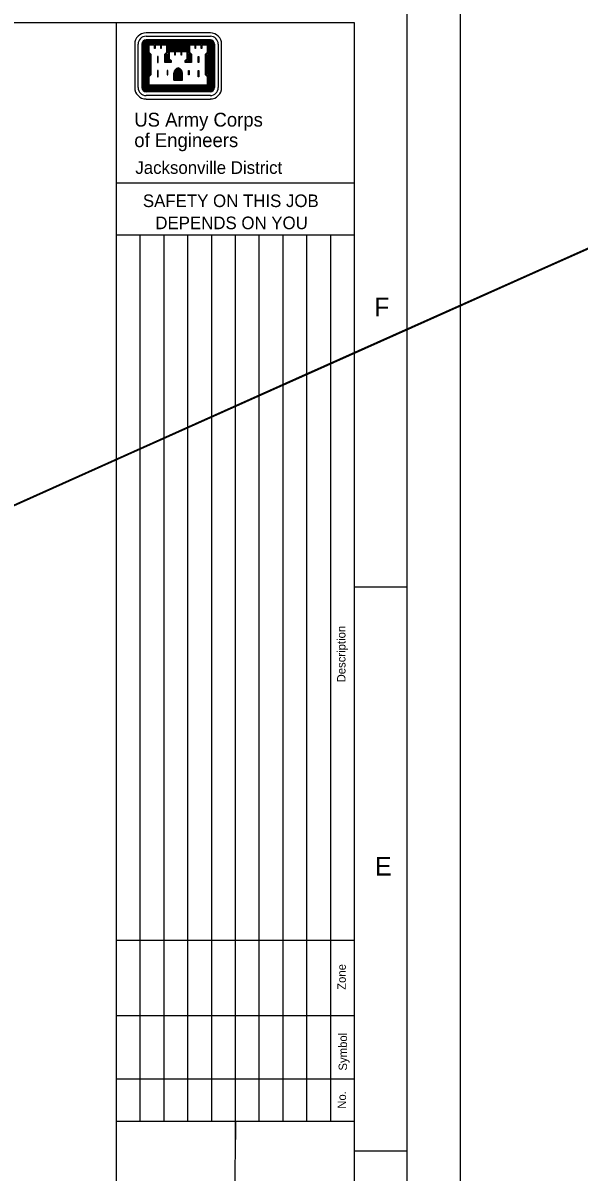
# Model space of a CAD drawing. Extents: x -295500 to 4194304, y 88492 to 2097152.
# Drawn here: x 1114915 to 1141196, y 687787 to 742112 of the extents above; entities that cross this region are included whole.
import ezdxf

# ---------------------------------------------------------------- set-up
doc = ezdxf.new("R2010")
doc.units = 0
for name, color, linetype in [('G-ANNO-NPLT', 7, 'Continuous'), ('G-ANNO-TEXT-LOGO', 7, 'Continuous'), ('G-ANNO-TEXT-TTLB', 7, 'Continuous'), ('G-ANNO-TTLB', 7, 'Continuous'), ('V-ANNO-SYMB', 7, 'Continuous')]:
    doc.layers.add(name, color=color, linetype=linetype)

msp = doc.modelspace()

# ---------------------------------------------------------------- linework, layer by layer
at = {"layer": 'G-ANNO-NPLT'}
msp.add_lwpolyline([(915578.8187059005, 747112.0946896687), (1135577.4987076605, 747112.0946896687), (1135577.4987076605, 577113.1146883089), (915578.8187059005, 577113.1146883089)], close=True, dxfattribs=at)
at = {"layer": 'G-ANNO-TEXT-LOGO'}
for p, q in [((1123770.5162011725, 741642.7534749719), (1120730.534441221, 741642.7534749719)), ((1120195.5376511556, 741107.7566849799), (1120195.5376511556, 739057.7689849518)), ((1120355.53669113, 739057.7689849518), (1120355.53669113, 741107.7566849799)), ((1120530.5356411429, 741107.7566849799), (1120530.5356411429, 739057.7689849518)), ((1120575.5353712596, 741107.7566849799), (1120575.5353712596, 739057.7689849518)), ((1120615.5351312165, 741107.7566849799), (1120615.5351312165, 739057.7689849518)), ((1120660.5348611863, 741107.7566849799), (1120660.5348611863, 739057.7689849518)), ((1120705.534591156, 741107.7566849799), (1120705.534591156, 739057.7689849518)), ((1120730.534441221, 741482.7544349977), (1123770.5162011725, 741482.7544349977)), ((1123770.5162011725, 741312.7554549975), (1120730.534441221, 741312.7554549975)), ((1123770.5162011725, 741267.7557250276), (1120730.534441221, 741267.7557250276)), ((1123770.5162011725, 741222.7559949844), (1120730.534441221, 741222.7559949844)), ((1123770.5162011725, 741182.7562350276), (1120730.534441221, 741182.7562350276)), ((1123770.5162011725, 741137.7565049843), (1120730.534441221, 741137.7565049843)), ((1120750.534321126, 741107.7566849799), (1120750.534321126, 739072.7688949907)), ((1120790.5340812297, 741107.7566849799), (1120790.5340812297, 739117.7686249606)), ((1121785.5281111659, 741097.7567450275), (1122715.5225312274, 741097.7567450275)), ((1121785.5281111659, 741052.7570149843), (1122715.5225312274, 741052.7570149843)), ((1121785.5281111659, 741012.7572550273), (1122715.5225312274, 741012.7572550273)), ((1123710.5165611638, 741107.7566849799), (1123710.5165611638, 739117.7686249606)), ((1123750.5163212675, 741107.7566849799), (1123750.5163212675, 739072.7688949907)), ((1123795.5160512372, 741107.7566849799), (1123795.5160512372, 739057.7689849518)), ((1123840.515781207, 741107.7566849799), (1123840.515781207, 739057.7689849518)), ((1123880.515541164, 741107.7566849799), (1123880.515541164, 739057.7689849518)), ((1123925.5152712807, 741107.7566849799), (1123925.5152712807, 739057.7689849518)), ((1123970.5150012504, 741107.7566849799), (1123970.5150012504, 739057.7689849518)), ((1124140.5139812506, 741107.7566849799), (1124140.5139812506, 739057.7689849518)), ((1124305.5129912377, 739057.7689849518), (1124305.5129912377, 741107.7566849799)), ((1120825.5338711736, 740672.7592950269), (1120825.5338711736, 739622.7655950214)), ((1120870.5336011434, 740627.7595649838), (1120870.5336011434, 739672.7652950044)), ((1121785.5281111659, 740967.7575249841), (1122715.5225312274, 740967.7575249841)), ((1121785.5281111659, 740922.7577950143), (1122715.5225312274, 740922.7577950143)), ((1121785.5281111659, 740882.758034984), (1122715.5225312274, 740882.758034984)), ((1121785.5281111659, 740837.7583050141), (1122715.5225312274, 740837.7583050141)), ((1123630.51704125, 740627.7595649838), (1123630.51704125, 739672.7652950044)), ((1123675.51677122, 740667.7593250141), (1123675.51677122, 739627.7655649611)), ((1122050.5265212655, 739412.7668549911), (1122050.5265212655, 739747.7648449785)), ((1122050.5265212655, 739412.7668549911), (1122450.5241212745, 739412.7668549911)), ((1122090.5262812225, 739412.7668549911), (1122090.5262812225, 739747.7648449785)), ((1122135.5260111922, 739412.7668549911), (1122135.5260111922, 739747.7648449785)), ((1122180.525741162, 739412.7668549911), (1122180.525741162, 739747.7648449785)), ((1122220.5255012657, 739412.7668549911), (1122220.5255012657, 739747.7648449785)), ((1122280.5251411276, 739412.7668549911), (1122280.5251411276, 739747.7648449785)), ((1122320.5249012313, 739412.7668549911), (1122320.5249012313, 739747.7648449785)), ((1122365.524631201, 739412.7668549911), (1122365.524631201, 739747.7648449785)), ((1122410.524361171, 739412.7668549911), (1122410.524361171, 739747.7648449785)), ((1122450.5241212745, 739412.7668549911), (1122450.5241212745, 739747.7648449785)), ((1123770.5162011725, 739027.7691650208), (1120730.534441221, 739027.7691650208)), ((1123770.5162011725, 738987.7694049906), (1120730.534441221, 738987.7694049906)), ((1123770.5162011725, 738942.7696750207), (1120730.534441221, 738942.7696750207)), ((1123770.5162011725, 738897.7699449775), (1120730.534441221, 738897.7699449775)), ((1123770.5162011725, 738857.7701850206), (1120730.534441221, 738857.7701850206)), ((1123750.5163212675, 739072.7688949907), (1120750.534321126, 739072.7688949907)), ((1123710.5165611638, 739117.7686249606), (1120790.5340812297, 739117.7686249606)), ((1123770.5162011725, 738682.7712350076), (1120730.534441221, 738682.7712350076)), ((1120730.534441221, 738517.7722249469), (1123770.5162011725, 738517.7722249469))]:
    msp.add_line(p, q, dxfattribs=at)
for points in [[(1120825.5338711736, 741107.7566849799), (1120825.5338711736, 740712.7590549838), (1120910.533361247, 740627.7595649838), (1120910.533361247, 739672.7652950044), (1120825.5338711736, 739582.7658349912), (1120825.5338711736, 739147.7684449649), (1123675.51677122, 739147.7684449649), (1123675.51677122, 739582.7658349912), (1123585.5173112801, 739672.7652950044), (1123585.5173112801, 740627.7595649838), (1123675.51677122, 740712.7590549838), (1123675.51677122, 741107.7566849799), (1123300.5190212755, 741107.7566849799), (1123010.5207612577, 741107.7566849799), (1122740.5223811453, 741107.7566849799), (1122740.5223811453, 740712.7590549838), (1122835.5218112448, 740627.7595649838), (1122835.5218112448, 740277.7616650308), (1122625.523071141, 740277.7616650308), (1122625.523071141, 740312.7614549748), (1122715.5225312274, 740402.7609149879), (1122715.5225312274, 740792.758574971), (1122340.5247811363, 740792.758574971), (1122050.5265212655, 740792.758574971), (1121785.5281111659, 740792.758574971), (1121785.5281111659, 740402.7609149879), (1121875.5275712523, 740312.7614549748), (1121875.5275712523, 740277.7616650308), (1121665.5288311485, 740277.7616650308), (1121665.5288311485, 740627.7595649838), (1121755.528291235, 740712.7590549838), (1121755.528291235, 741107.7566849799), (1121380.5305411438, 741107.7566849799), (1121090.5322811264, 741107.7566849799), (1120825.5338711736, 741107.7566849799)], [(1120865.5336311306, 741062.7569550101), (1120865.5336311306, 740732.7589350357), (1120955.5330912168, 740642.7594750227), (1120955.5330912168, 739652.7654150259), (1120865.5336311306, 739562.7659550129), (1120865.5336311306, 739192.768175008), (1123635.517011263, 739192.768175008), (1123635.517011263, 739562.7659550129), (1123540.5175811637, 739652.7654150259), (1123540.5175811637, 740642.7594750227), (1123635.517011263, 740732.7589350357), (1123635.517011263, 741062.7569550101), (1123365.5186311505, 741062.7569550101), (1123365.5186311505, 740907.7578849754), (1123340.5187812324, 740907.7578849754), (1123340.5187812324, 741062.7569550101), (1123075.5203712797, 741062.7569550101), (1123075.5203712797, 740907.7578849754), (1123055.5204912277, 740907.7578849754), (1123055.5204912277, 741062.7569550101), (1122785.522111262, 741062.7569550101), (1122785.522111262, 740732.7589350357), (1122875.5215712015, 740642.7594750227), (1122875.5215712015, 740237.7619050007), (1122585.523311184, 740237.7619050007), (1122585.523311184, 740332.7613350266), (1122675.5227712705, 740422.7607949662), (1122675.5227712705, 740752.7588150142), (1122405.524391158, 740752.7588150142), (1122405.524391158, 740597.7597449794), (1122385.5245112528, 740597.7597449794), (1122385.5245112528, 740752.7588150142), (1122115.5261311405, 740752.7588150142), (1122115.5261311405, 740597.7597449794), (1122090.5262812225, 740597.7597449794), (1122090.5262812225, 740752.7588150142), (1121825.5278712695, 740752.7588150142), (1121825.5278712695, 740422.7607949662), (1121915.5273312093, 740332.7613350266), (1121915.5273312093, 740237.7619050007), (1121625.5290711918, 740237.7619050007), (1121625.5290711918, 740642.7594750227), (1121715.5285311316, 740732.7589350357), (1121715.5285311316, 741062.7569550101), (1121450.5301211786, 741062.7569550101), (1121450.5301211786, 740907.7578849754), (1121425.5302712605, 740907.7578849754), (1121425.5302712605, 741062.7569550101), (1121155.531891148, 741062.7569550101), (1121155.531891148, 740907.7578849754), (1121135.532011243, 740907.7578849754), (1121135.532011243, 741062.7569550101), (1120865.5336311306, 741062.7569550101)], [(1121275.5311711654, 740527.7601650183), (1121275.5311711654, 740237.7619050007), (1121305.530991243, 740237.7619050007), (1121305.530991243, 740527.7601650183), (1121275.5311711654, 740527.7601650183)], [(1121735.5284111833, 740632.7595349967), (1121710.528561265, 740607.7596850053), (1121710.528561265, 740322.7613950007), (1121805.5279912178, 740322.7613950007), (1121740.528381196, 740387.7610050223), (1121740.528381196, 740637.7595050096)], [(1122765.5222312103, 740632.7595349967), (1122790.5220812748, 740607.7596850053), (1122790.5220812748, 740322.7613950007), (1122700.5226211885, 740322.7613950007), (1122760.5222611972, 740387.7610050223), (1122760.5222611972, 740637.7595050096)], [(1123220.519501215, 740527.7601650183), (1123220.519501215, 740237.7619050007), (1123195.5196511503, 740237.7619050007), (1123195.5196511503, 740527.7601650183), (1123220.519501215, 740527.7601650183)], [(1121275.5311711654, 739862.7641549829), (1121275.5311711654, 739567.7659250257), (1121305.530991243, 739567.7659250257), (1121305.530991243, 739862.7641549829), (1121275.5311711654, 739862.7641549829)], [(1121735.5284111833, 739862.7641549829), (1121735.5284111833, 739657.7653849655), (1121760.528261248, 739657.7653849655), (1121760.528261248, 739862.7641549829), (1121735.5284111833, 739862.7641549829)], [(1122765.5222312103, 739862.7641549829), (1122765.5222312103, 739657.7653849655), (1122740.5223811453, 739657.7653849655), (1122740.5223811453, 739862.7641549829), (1122765.5222312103, 739862.7641549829)], [(1123220.519501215, 739862.7641549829), (1123220.519501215, 739567.7659250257), (1123195.5196511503, 739567.7659250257), (1123195.5196511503, 739862.7641549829), (1123220.519501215, 739862.7641549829)]]:
    msp.add_lwpolyline(points, dxfattribs=at)
for centre, major_axis, ratio, start_param, end_param in [((1120731.8048306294, 741108.6151385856), (535.6894959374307, 0), 0.99963998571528, 1.5707800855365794, 3.141576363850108), ((1123767.3785251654, 741108.5674731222), (535.6894959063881, 0), 0.9996399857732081, 6.283169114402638, 7.853965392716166), ((1120731.8048306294, 741108.6151385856), (374.4914271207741, 0), 0.9996399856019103, 1.5707800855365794, 3.141576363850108), ((1120731.8048306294, 741108.6151385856), (200.8836685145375, 0), 0.9996399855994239, 1.5707800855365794, 3.141576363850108), ((1120731.8048306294, 741108.6151385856), (157.4827590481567, 0), 0.9996399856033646, 1.5707800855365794, 3.141576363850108), ((1120731.8048306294, 741108.6151385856), (114.08194856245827, 0), 0.9996399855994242, 1.5707800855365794, 3.141576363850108), ((1120731.8048306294, 741108.6151385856), (70.68113475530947, 0), 0.9996399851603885, 1.5707800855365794, 3.141576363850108), ((1120731.8048306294, 741108.6151385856), (27.280320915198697, 0), 0.9996399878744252, 1.5707800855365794, 3.141576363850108), ((1123767.3785251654, 741108.5674731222), (27.280320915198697, 0), 0.9996399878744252, 6.283169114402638, 7.853965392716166), ((1123767.3785251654, 741108.5674731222), (70.68113466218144, 0), 0.999639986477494, 6.283169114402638, 7.853965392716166), ((1123767.3785251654, 741108.5674731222), (114.08194846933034, 0), 0.9996399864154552, 6.283169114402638, 7.853965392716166), ((1123767.3785251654, 741108.5674731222), (157.48275895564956, 0), 0.9996399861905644, 6.283169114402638, 7.853965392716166), ((1123767.3785251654, 741108.5674731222), (200.88366842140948, 0), 0.9996399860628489, 6.283169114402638, 7.853965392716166), ((1123767.3785251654, 741108.5674731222), (374.49142660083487, 0), 0.9996399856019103, 6.283169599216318, 7.853965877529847), ((1122324.3599183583, 739725.4688298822), (-277.6705194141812, 3.4004831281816e-14), 0.9996399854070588, 4.9858321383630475, 6.214359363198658), ((1122324.3599183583, 739725.4688298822), (-234.2697347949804, 2.8689768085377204e-14), 0.9996399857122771, 4.947465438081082, 6.214359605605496), ((1122174.779969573, 739725.4711786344), (234.2697368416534, 0), 0.9996399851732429, 0.06879472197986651, 1.335688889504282), ((1122174.779969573, 739725.4711786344), (277.6705215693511, 0), 0.9996399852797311, 0.06879467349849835, 1.298419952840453), ((1122324.3599183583, 739725.4688298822), (-190.86890076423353, 2.337469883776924e-14), 0.9996399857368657, 4.947465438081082, 6.214359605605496), ((1122324.3599183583, 739725.4688298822), (-147.4681138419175, 1.8059635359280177e-14), 0.9996399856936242, 4.9474653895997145, 6.21435955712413), ((1122174.779969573, 739725.4711786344), (104.0672750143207, 0), 0.9996399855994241, 0.06879443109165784, 1.3356885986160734), ((1122174.779969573, 739725.4711786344), (147.46811562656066, 0), 0.9996399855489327, 0.068794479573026, 1.3356886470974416), ((1122174.779969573, 739725.4711786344), (190.86890273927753, 0), 0.9996399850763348, 0.06879481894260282, 1.3356889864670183), ((1122324.3599183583, 739725.4688298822), (-104.06727339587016, 1.274456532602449e-14), 0.9996399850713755, 4.947464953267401, 6.2143591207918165), ((1120731.772574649, 739055.879026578), (-535.6894941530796, 6.560304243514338e-14), 0.999639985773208, 6.283170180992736, 7.853966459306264), ((1120731.772574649, 739055.879026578), (-374.49142660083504, 4.586197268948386e-14), 0.9996399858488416, 6.283169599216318, 7.853965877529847), ((1120731.772574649, 739055.879026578), (-200.88366785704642, 2.4601154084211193e-14), 0.9996399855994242, 6.2831701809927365, 7.853966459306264), ((1120731.772574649, 739055.879026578), (-157.48275853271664, 1.9286075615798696e-14), 0.9996399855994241, 6.2831701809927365, 7.853966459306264), ((1120731.772574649, 739055.879026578), (-114.08194809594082, 1.3971009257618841e-14), 0.9996399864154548, 6.2831701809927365, 7.853966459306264), ((1120731.772574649, 739055.879026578), (-70.68113443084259, 8.655942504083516e-15), 0.9996399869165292, 6.2831701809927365, 7.853966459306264), ((1120731.772574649, 739055.879026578), (-27.280320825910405, 3.3408757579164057e-15), 0.999639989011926, 6.2831701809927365, 7.853966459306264), ((1123767.346269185, 739055.8313609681), (535.6894952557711, 0), 0.9996399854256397, 4.71237332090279, 6.283169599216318), ((1123767.346269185, 739055.8313609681), (-374.49142589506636, 4.5861972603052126e-14), 0.9996399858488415, 1.570781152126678, 3.1415774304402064), ((1123767.346269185, 739055.8313609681), (200.88366823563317, 0), 0.9996399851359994, 4.71237332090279, 6.283169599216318), ((1123767.346269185, 739055.8313609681), (157.4827588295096, 0), 0.999639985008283, 4.71237332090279, 6.283169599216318), ((1123767.346269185, 739055.8313609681), (114.08194840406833, 0), 0.9996399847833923, 4.71237332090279, 6.283169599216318), ((1123767.346269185, 739055.8313609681), (70.68113465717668, 0), 0.9996399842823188, 4.71237332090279, 6.283169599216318), ((1123767.346269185, 739055.8313609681), (27.280320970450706, 0), 0.9996399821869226, 4.71237332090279, 6.283169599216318)]:
    msp.add_ellipse(centre, major_axis=major_axis, ratio=ratio, start_param=start_param, end_param=end_param, dxfattribs=at)
at = {"layer": 'G-ANNO-TTLB'}
for p, q in [((1119326.1851971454, 742112.1246896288), (1119326.1851971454, 582113.0846883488)), ((1119327.5962075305, 734550.5892127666), (1130577.5287076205, 734550.5892127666)), ((1119296.8200647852, 732094.4645139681), (1130546.7525648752, 732094.4645139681)), ((1120443.0284441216, 732094.4645139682), (1120443.0284441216, 690198.7862496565)), ((1121568.0239441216, 732094.4645139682), (1121568.0239441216, 690198.7862496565)), ((1122693.0194441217, 732094.4645139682), (1122693.0194441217, 690198.7862496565)), ((1123818.0149441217, 732094.4645139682), (1123818.0149441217, 690198.7862496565)), ((1124943.0104441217, 732094.4645139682), (1124943.0104441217, 690198.7862496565)), ((1126068.0059441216, 732094.4645139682), (1126068.0059441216, 690198.7862496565)), ((1127193.0014441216, 732094.4645139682), (1127193.0014441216, 690198.7862496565)), ((1128317.9969441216, 732094.4645139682), (1128317.9969441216, 690198.7862496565)), ((1129442.9924441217, 732094.4645139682), (1129442.9924441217, 690198.7862496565)), ((1133077.5137076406, 715437.0655515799), (1130577.5287076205, 715437.0655515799)), ((1119327.5962075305, 698750.2562425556), (1130577.5287076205, 698750.2562425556)), ((1119327.5962075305, 695191.5190431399), (1130577.5287076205, 695191.5190431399)), ((1119327.5962075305, 692191.5370430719), (1130577.5287076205, 692189.2539785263)), ((1119327.5962075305, 690198.7862496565), (1130577.5287076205, 690198.7862496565)), ((1124919.4957649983, 647220.3525255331), (1124952.5624575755, 690198.7862496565)), ((1124952.5624575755, 690198.7862496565), (1124951.200315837, 688428.3425231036)), ((1133077.5137076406, 688772.17221158), (1130577.5287076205, 688772.17221158))]:
    msp.add_line(p, q, dxfattribs=at)
for points in [[(918078.8037059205, 579613.0996883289), (1133077.5137076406, 579613.0996883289), (1133077.5137076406, 744612.1096896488), (918078.8037059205, 744612.1096896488)], [(1130577.5287076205, 742112.1246896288), (924328.7662059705, 742112.1246896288), (924328.7662059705, 582113.0846883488), (1130577.5287076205, 582113.0846883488)]]:
    msp.add_lwpolyline(points, close=True, dxfattribs=at)
at = {"layer": 'V-ANNO-SYMB'}
msp.add_spline([(1091921.4026075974, 709237.9102775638), (1091907.9026075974, 709215.4102775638), (1091912.4026075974, 709192.9102789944), (1091925.902606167, 709201.9102789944), (1091925.902606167, 709201.9102789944), (1091921.4026075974, 709237.9102775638)], degree=3, dxfattribs=at)

# ---------------------------------------------------------------- texts
at = {"layer": 'G-ANNO-TEXT-TTLB'}
for s, height, p in [('US Army Corps', 654.2960742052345, (1120175.5377712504, 737212.7800549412)), ('of Engineers', 654.2960742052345, (1120175.5377712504, 736242.7858749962)), ('Jacksonville District', 594.98643006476, (1120225.5374712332, 734977.7934649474)), ('SAFETY ON THIS JOB', 595, (1120581.9436649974, 733408.4414311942)), ('DEPENDS ON YOU', 595, (1121170.5945796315, 732363.4414311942))]:
    msp.add_text(s, height=height, dxfattribs=at).set_placement(p)
for s, p in [('Description', (1130158.3873789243, 710935.4867789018)), ('Zone', (1130173.3247769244, 696400.0096261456)), ('Symbol', (1130231.9575723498, 692584.0812695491)), ('No.', (1130181.8776587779, 690777.9268508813))]:
    msp.add_text(s, height=399.99840000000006, rotation=89.99999846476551, dxfattribs=at).set_placement(p)
at = {"layer": 'G-ANNO-TTLB'}
for s, p in [('F', (1131516.5239007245, 728246.0315158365)), ('E', (1131555.8330767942, 701803.9371686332))]:
    msp.add_text(s, height=874.9965003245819, dxfattribs=at).set_placement(p)

doc.saveas('drawing.dxf')
